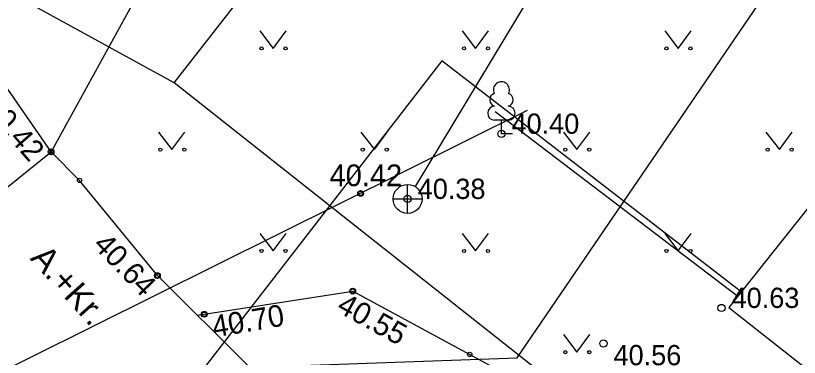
# Model space of a CAD drawing. Extents: x 641898 to 642452, y 6471715 to 6472255.
# Drawn here: x 641996.97 to 642024.06, y 6472085.4 to 6472097.21 of the extents above; entities that cross this region are included whole.
import ezdxf

# ---------------------------------------------------------------- set-up
doc = ezdxf.new("R2010")
doc.units = 0
for name, color, linetype in [('HALJASTUS', 7, 'Continuous'), ('HOONE', 7, 'Continuous'), ('KKAEV', 7, 'Continuous'), ('KORGUS-EH2000', 7, 'Continuous'), ('KTRASS', 7, 'Continuous'), ('MOOTMPUNKT', 7, 'Continuous'), ('MOOTPIIR', 7, 'Continuous'), ('PIIR', 7, 'Continuous'), ('PUU', 7, 'Continuous'), ('SITRASS', 7, 'Continuous'), ('SKTRASS', 7, 'Continuous'), ('TEE', 7, 'Continuous'), ('TTRASS', 7, 'Continuous')]:
    doc.layers.add(name, color=color, linetype=linetype)

msp = doc.modelspace()

# ---------------------------------------------------------------- linework, layer by layer
at = {"layer": 'HALJASTUS'}
for p, q in [((642005.408, 6472096.682), (642005.871, 6472096.075)), ((642005.871, 6472096.075), (642006.317, 6472096.682)), ((642012.408, 6472096.682), (642012.871, 6472096.075)), ((642012.871, 6472096.075), (642013.317, 6472096.682)), ((642019.408, 6472096.682), (642019.871, 6472096.075)), ((642019.871, 6472096.075), (642020.317, 6472096.682)), ((642001.908, 6472093.182), (642002.371, 6472092.575)), ((642002.371, 6472092.575), (642002.817, 6472093.182)), ((642008.908, 6472093.182), (642009.371, 6472092.575)), ((642009.371, 6472092.575), (642009.817, 6472093.182)), ((642015.908, 6472093.182), (642016.371, 6472092.575)), ((642016.371, 6472092.575), (642016.817, 6472093.182)), ((642022.908, 6472093.182), (642023.371, 6472092.575)), ((642023.371, 6472092.575), (642023.817, 6472093.182)), ((642005.408, 6472089.682), (642005.871, 6472089.075)), ((642005.871, 6472089.075), (642006.317, 6472089.682)), ((642012.408, 6472089.682), (642012.871, 6472089.075)), ((642012.871, 6472089.075), (642013.317, 6472089.682)), ((642019.408, 6472089.682), (642019.871, 6472089.075)), ((642019.871, 6472089.075), (642020.317, 6472089.682)), ((642015.908, 6472086.182), (642016.371, 6472085.575)), ((642016.371, 6472085.575), (642016.817, 6472086.182))]:
    msp.add_line(p, q, dxfattribs=at)
msp.add_lwpolyline([(642003.529, 6472102.174), (642000.861, 6472097.337), (641998.193, 6472092.499)], dxfattribs=at)
for centre in [(642005.47, 6472096.075), (642006.299, 6472096.075), (642012.47, 6472096.075), (642013.299, 6472096.075), (642019.47, 6472096.075), (642020.299, 6472096.075), (642001.97, 6472092.575), (642002.799, 6472092.575), (642008.97, 6472092.575), (642009.799, 6472092.575), (642015.97, 6472092.575), (642016.799, 6472092.575), (642022.97, 6472092.575), (642023.799, 6472092.575), (642005.47, 6472089.075), (642006.299, 6472089.075), (642012.47, 6472089.075), (642013.299, 6472089.075), (642019.47, 6472089.075), (642020.299, 6472089.075), (642015.97, 6472085.575), (642016.799, 6472085.575)]:
    msp.add_circle(centre, 0.055, dxfattribs=at)
at = {"layer": 'HOONE'}
msp.add_lwpolyline([(642065.653, 6472064.719), (642027.624, 6472094.67), (642021.622, 6472087.119), (642059.651, 6472057.168), (642065.653, 6472064.719)], dxfattribs=at)
at = {"layer": 'KKAEV'}
for p, q in [((642010.52, 6472090.371), (642010.52, 6472091.371)), ((642010.02, 6472090.871), (642011.02, 6472090.871))]:
    msp.add_line(p, q, dxfattribs=at)
msp.add_circle((642010.52, 6472090.871), 0.5, dxfattribs=at)
at = {"layer": 'KORGUS-EH2000'}
for centre, radius in [((642013.763, 6472093.123), 0.125), ((641998.193, 6472092.499), 0.1), ((642008.895, 6472091.063), 0.1), ((642010.52, 6472090.871), 0.125), ((642001.868, 6472088.221), 0.1), ((642008.621, 6472087.685), 0.1), ((642021.371, 6472087.104), 0.125), ((642003.491, 6472086.884), 0.1)]:
    msp.add_circle(centre, radius, dxfattribs=at)
at = {"layer": 'KTRASS'}
msp.add_lwpolyline([(641991.013, 6472082.193), (642014.668, 6472093.944)], dxfattribs=at)
at = {"layer": 'MOOTMPUNKT'}
for centre in [(641998.193, 6472092.499), (641999.18, 6472091.513), (642008.895, 6472091.063), (642001.868, 6472088.221), (642008.621, 6472087.685), (642003.491, 6472086.884), (642012.666, 6472085.497)]:
    msp.add_circle(centre, 0.075, dxfattribs=at)
at = {"layer": 'MOOTPIIR'}
msp.add_lwpolyline([(642014.306, 6472085.384), (642027.67, 6472104.979), (642055.501, 6472084.843), (642081.563, 6472094.262), (642123.938, 6472142.273), (642065.721, 6472244.475), (642008.922, 6472196.948), (642003.347, 6472200.453), (641979.65, 6472162.756), (641979.65, 6472162.756), (641986.045, 6472158.736), (642004.269, 6472142.365), (641987.048, 6472123.488), (641970.482, 6472097.889), (641986.758, 6472084.396)], close=True, dxfattribs=at)
at = {"layer": 'PIIR'}
for p, q in [((642002.45, 6472094.89), (642016.19, 6472112.51)), ((642002.45, 6472094.89), (641997.45, 6472097.63)), ((642017.33, 6472083.13), (642002.45, 6472094.89))]:
    msp.add_line(p, q, dxfattribs=at)
at = {"layer": 'PUU'}
for p, q in [((642014.003, 6472093.598), (642013.523, 6472093.598)), ((642013.763, 6472093.123), (642013.763, 6472093.598)), ((642014.143, 6472093.123), (642013.763, 6472093.123))]:
    msp.add_line(p, q, dxfattribs=at)
msp.add_circle((642017.289, 6472085.874), 0.125, dxfattribs=at)
for centre, radius, start, end in [((642013.763, 6472094.643), 0.277, 332.5799, 207.4201), ((642013.593, 6472094.296), 0.233, 109.0217, 253.1415), ((642013.933, 6472094.296), 0.233, 286.8508, 70.9859), ((642013.526, 6472093.835), 0.238, 90.0016, 269.3953), ((642014, 6472093.835), 0.238, 270.6047, 89.9984)]:
    msp.add_arc(centre, radius, start, end, dxfattribs=at)
at = {"layer": 'SITRASS'}
msp.add_lwpolyline([(642022.056, 6472087.662), (642011.704, 6472095.646), (641989.129, 6472066.508), (641984.461, 6472060.483)], dxfattribs=at)
at = {"layer": 'SKTRASS'}
msp.add_line((642022.933, 6472111.454), (642010.778, 6472091.299), dxfattribs=at)
at = {"layer": 'TEE'}
for points in [[(641975.171, 6472107.781), (641979.834, 6472105.5), (641983.935, 6472103.138), (641986.452, 6472101.438), (641989.645, 6472098.476), (641992.737, 6472094.423), (641995.507, 6472090.345), (641998.193, 6472092.499), (641996.353, 6472095.149), (641994.781, 6472097.254), (641993.534, 6472099.522), (641992.261, 6472102.125), (641992.086, 6472103.239)], [(641992.618, 6472094.578), (641991.404, 6472091.461), (641995.031, 6472087.196), (641995.679, 6472085.928), (641995.92, 6472084.762), (642004.997, 6472085.116), (642001.868, 6472088.221), (641999.18, 6472091.513), (641998.193, 6472092.499)], [(642003.242, 6472086.858), (642003.491, 6472086.884), (642008.621, 6472087.685), (642012.666, 6472085.497), (642017.972, 6472082.626), (642023.535, 6472079.305), (642024.936, 6472081.09), (642027.104, 6472079.457), (642025.745, 6472077.14), (642035.04, 6472069.842), (642036.698, 6472071.809), (642039.147, 6472069.927), (642037.552, 6472067.801), (642047.021, 6472060.414), (642048.68, 6472062.323), (642050.484, 6472060.969), (642049.417, 6472058.038), (642058.292, 6472050.781), (642057.815, 6472050.19)]]:
    msp.add_lwpolyline(points, dxfattribs=at)
at = {"layer": 'TTRASS'}
msp.add_lwpolyline([(642013.545, 6472093.89), (642021.935, 6472087.511)], dxfattribs=at)

# ---------------------------------------------------------------- texts
at = {"layer": 'KORGUS-EH2000'}
for s, rotation, p in [('40.42', 311.0576, (641995.807, 6472094.001)), ('40.64', 313.9531, (641999.61, 6472089.25)), ('40.55', 331.1827, (642008.024, 6472087)), ('40.70', 9.6385, (642003.825, 6472086.081))]:
    msp.add_text(s, height=0.75, rotation=rotation, dxfattribs=at).set_placement(p)
for s, height, p in [('40.40', 0.7, (642014.113, 6472093.123)), ('40.42', 0.75, (642007.822, 6472091.313)), ('40.38', 0.7, (642010.87, 6472090.871)), ('40.63', 0.7, (642021.721, 6472087.104)), ('40.56', 0.7, (642017.639, 6472085.124))]:
    msp.add_text(s, height=height, dxfattribs=at).set_placement(p)
at = {"layer": 'TEE'}
msp.add_text('A.+Kr.', height=0.85, rotation=311.8661, dxfattribs=at).set_placement((641997.441, 6472088.801))

doc.saveas('drawing.dxf')
